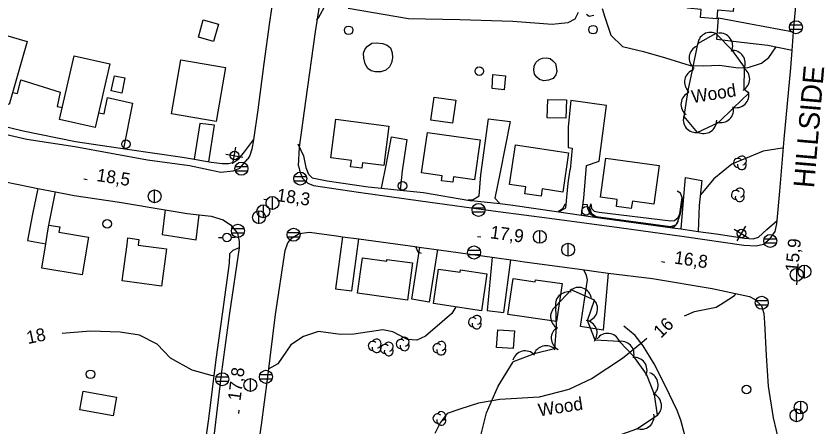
# Model space of a CAD drawing. Extents: x 646142 to 649934, y 5874075 to 5876351.
# Drawn here: x 647384.4 to 647570.1, y 5875028.6 to 5875124.3 of the extents above; entities that cross this region are included whole.
import ezdxf

# ---------------------------------------------------------------- set-up
doc = ezdxf.new("R2010")
doc.units = 0
for name, color, linetype in [('Niveau 1', 7, 'Continuous'), ('Niveau 15', 7, 'Continuous'), ('Niveau 19', 7, 'Continuous'), ('Niveau 2', 7, 'Continuous'), ('Niveau 21', 7, 'Continuous'), ('Niveau 22', 7, 'Continuous'), ('Niveau 3', 7, 'Continuous'), ('Niveau 31', 7, 'Continuous'), ('Niveau 36', 7, 'Continuous'), ('Niveau 37', 7, 'Continuous'), ('Niveau 4', 7, 'Continuous'), ('Niveau 44', 7, 'Continuous')]:
    doc.layers.add(name, color=color, linetype=linetype)

msp = doc.modelspace()

# ---------------------------------------------------------------- linework, layer by layer
at = {"layer": 'Niveau 1'}
for points in [[(647454.48, 5875123.38), (647454.96, 5875123.78), (647456.71, 5875127.05)], [(647521.11, 5875125.96), (647521.71, 5875123.96), (647523.15, 5875119.77), (647525.87, 5875117.15), (647530.71, 5875115.95), (647535.85, 5875114.49), (647541.6, 5875112.7), (647544.71, 5875112.63), (647548.5, 5875112.75), (647552.86, 5875112.18), (647555.16, 5875112.25), (647558.28, 5875113.27), (647559.99, 5875114.59), (647561.56, 5875116.82), (647561.66, 5875116.97)], [(647517.44, 5875124.66), (647518.06, 5875124.21), (647519.13, 5875124.43)]]:
    msp.add_lwpolyline(points, dxfattribs=at)
at = {"layer": 'Niveau 19'}
for points in [[(647565.42, 5875116.2), (647559.72, 5875117.37), (647553.61, 5875118.03), (647547.85, 5875118.73), (647548.24, 5875123.83), (647555.71, 5875122.38), (647565.77, 5875120.55)], [(647383.55, 5875106.43), (647384.69, 5875106.16), (647385.47, 5875109.33), (647394.66, 5875106.51), (647393.94, 5875103.15), (647395.18, 5875102.88)], [(647403.6, 5875101.66), (647404.92, 5875101.46), (647405.69, 5875105.26), (647411.53, 5875103.93), (647409.45, 5875093.33)], [(647513.77, 5875104.53), (647513.14, 5875098.37), (647513.21, 5875093.57), (647514.14, 5875093.42), (647513.66, 5875088.41)], [(647516.32, 5875077.77), (647516.82, 5875081.79), (647517.42, 5875089.35), (647520.44, 5875090.4), (647522.14, 5875103.37), (647513.77, 5875104.53)], [(647490.66, 5875081.19), (647492.41, 5875082.29), (647492.83, 5875087.18), (647494.61, 5875100.26), (647499.68, 5875099.61), (647497.29, 5875087.85), (647496.07, 5875081.73), (647497.27, 5875080.49)], [(647429.35, 5875090.22), (647430.69, 5875098.82), (647427.26, 5875099.19), (647425.93, 5875090.85)], [(647469.64, 5875084.1), (647470.79, 5875089.87), (647472, 5875096.1), (647475.56, 5875095.41), (647474.45, 5875088.15), (647473.97, 5875083.64)], [(647510.99, 5875078.56), (647512.63, 5875079.53), (647513.2, 5875085.24), (647513.66, 5875088.41)], [(647539.5, 5875074.57), (647540.09, 5875081.21), (647540.58, 5875086.57), (647544.37, 5875085.9), (647543.7, 5875080.07), (647543.48, 5875074.01)], [(647389.43, 5875084.02), (647388.19, 5875078.01), (647387.07, 5875071.9), (647391.32, 5875071.12)], [(647392.06, 5875075.48), (647393.55, 5875083.23)], [(647419.15, 5875079.04), (647418.45, 5875073.32), (647426.38, 5875072.03), (647427.06, 5875077.9)], [(647460.57, 5875072.76), (647458.92, 5875060.6), (647462.68, 5875060.16), (647464.35, 5875072.25)], [(647482.67, 5875069.76), (647480.75, 5875057.49), (647476.72, 5875058.18), (647478.58, 5875070.32)], [(647495.44, 5875068), (647494.29, 5875055.53), (647498.12, 5875055.1)], [(647499.7, 5875067.39), (647498.12, 5875055.1)], [(647522.54, 5875064.3), (647521.32, 5875050.98), (647516.06, 5875051.84), (647517.69, 5875062.69), (647517.49, 5875063.73), (647516.81, 5875065.03)]]:
    msp.add_lwpolyline(points, dxfattribs=at)
at = {"layer": 'Niveau 2'}
for points in [[(647563.41, 5875093.37), (647563.12, 5875093.41), (647558.66, 5875092.74), (647551.35, 5875089.71), (647547.12, 5875086.23), (647544.54, 5875083.09), (647543.97, 5875082.48)], [(647490.94, 5875081.37), (647489.86, 5875081.3)], [(647540.13, 5875081.64), (647539.91, 5875081.65), (647539.26, 5875077.84), (647538.49, 5875075.8), (647537.71, 5875074.91), (647537.31, 5875074.88)], [(647512.7, 5875080.27), (647512.42, 5875080.26), (647511.88, 5875079.29), (647510.81, 5875078.58)], [(647527.24, 5875076.25), (647526.62, 5875076.36), (647519.17, 5875077.47), (647518.3, 5875078.02), (647517.75, 5875079.35), (647517.66, 5875080.2), (647516.63, 5875080.25)], [(647477.81, 5875070.43), (647477.62, 5875070.3), (647478.08, 5875069.25), (647478.85, 5875068.92)], [(647540.35, 5875054.34), (647542.64, 5875055.34), (647547.73, 5875056.3), (647549.37, 5875057.33), (647551.99, 5875059.04), (647552.33, 5875059.51)], [(647486.99, 5875056.38), (647486.05, 5875054.84), (647483.8, 5875052.94), (647479.9, 5875049.61), (647477.84, 5875048.66), (647475.73, 5875048.8), (647472.29, 5875050.59), (647469.97, 5875051.06), (647463.21, 5875050.04), (647460.08, 5875049.96), (647454.94, 5875050.67), (647451.45, 5875049.51), (647448.51, 5875047.55), (647445.48, 5875043.09), (647443.32, 5875041.99)], [(647430.55, 5875040.39), (647430.17, 5875040.36), (647425.44, 5875041.63), (647420.43, 5875044.48), (647417.31, 5875047.69), (647413.19, 5875049.83), (647408.7, 5875050.54), (647401.76, 5875050.72), (647395.12, 5875050.18)], [(647531.52, 5875049.03), (647530.45, 5875048.11), (647525.88, 5875044.36), (647518.79, 5875039.73), (647513.34, 5875037.11), (647506.41, 5875035.38), (647497.2, 5875034.82), (647492.28, 5875033.92), (647487.87, 5875032.56), (647484.95, 5875031.52), (647483.3, 5875029.39), (647482.04, 5875026.89)]]:
    msp.add_lwpolyline(points, dxfattribs=at)
at = {"layer": 'Niveau 21'}
for points in [[(647450.3, 5875089.3), (647450.51, 5875088.27), (647451.16, 5875086.49), (647452.45, 5875085.24), (647453.79, 5875084.68), (647464.3, 5875083.18), (647478.7, 5875081.14), (647496.87, 5875078.67), (647508.8, 5875077.08), (647525.09, 5875074.88), (647540.22, 5875072.79), (647554.18, 5875070.82), (647557, 5875070.64), (647558.71, 5875071.04), (647560.32, 5875072.35), (647561.43, 5875073.97), (647561.83, 5875075.74), (647561.9, 5875076.55), (647562.54, 5875083.43), (647563.6, 5875095.54), (647565.09, 5875112.17), (647565.42, 5875116.2), (647565.77, 5875120.55), (647565.98, 5875123.22), (647567.26, 5875137.4)], [(647444.28, 5875128.19), (647443.51, 5875122.77), (647442.17, 5875113.19), (647440.75, 5875102.37), (647439.78, 5875095.38), (647439.4, 5875093.21), (647438.88, 5875091.71), (647438.43, 5875090.96)], [(647450.3, 5875089.3), (647450.48, 5875093.62), (647451.98, 5875104.36), (647454.26, 5875120.59), (647455.14, 5875126.53)], [(647373.66, 5875098.57), (647386.89, 5875095.51), (647398.13, 5875093.84), (647415.05, 5875090.71), (647424.87, 5875089.35), (647432.17, 5875087.83), (647435.02, 5875088.14), (647436.57, 5875088.76), (647438.43, 5875090.96)], [(647378.44, 5875086.24), (647387.58, 5875084.37), (647389.43, 5875084.02), (647393.55, 5875083.23), (647397.9, 5875082.4), (647408.53, 5875080.79), (647419.15, 5875079.04), (647424.26, 5875078.2), (647427.06, 5875077.9), (647429.9, 5875077.6), (647432.67, 5875076.72), (647434.42, 5875075.51), (647436.01, 5875073.59), (647436.44, 5875071.67), (647436.46, 5875070.16)], [(647440.08, 5875017.86), (647441.66, 5875028.86), (647443.01, 5875039.5), (647444.94, 5875054.59), (647447.12, 5875069.59), (647447.75, 5875071.38), (647448.8, 5875072.52), (647450.44, 5875073.49), (647452.85, 5875073.84), (647459.1, 5875072.96), (647460.57, 5875072.76), (647464.35, 5875072.25), (647476.33, 5875070.63), (647478.99, 5875070.27), (647483.55, 5875069.64), (647492.02, 5875068.49), (647495.44, 5875068), (647500.98, 5875067.21), (647503.01, 5875066.92), (647517.57, 5875064.93), (647519.19, 5875064.71), (647522.54, 5875064.3), (647532.87, 5875063.06), (647546.74, 5875060.73), (647555.45, 5875058.82), (647556.68, 5875058.24), (647558.24, 5875056.66), (647558.78, 5875054.87), (647559.01, 5875052.69), (647559.34, 5875045.08), (647559.85, 5875037.95), (647560.97, 5875030.53), (647562.41, 5875024.64)], [(647436.46, 5875070.16), (647434.19, 5875054.93), (647432.34, 5875041.24), (647430.5, 5875026.28), (647428.03, 5875008.35), (647426.81, 5874998.74), (647426.04, 5874997.17), (647424.61, 5874995.17), (647423, 5874993.86), (647420.63, 5874993.16), (647418.79, 5874992.86), (647416.91, 5874993.03), (647404.42, 5874995.61), (647383.56, 5874999.21)]]:
    msp.add_lwpolyline(points, dxfattribs=at)
at = {"layer": 'Niveau 22'}
for points in [[(647377.63, 5875099.47), (647386.01, 5875097.49), (647398.26, 5875095.01), (647410.32, 5875093.2), (647423.18, 5875091.36), (647425.05, 5875091.02), (647429.87, 5875090.12), (647431.2, 5875089.97), (647432.44, 5875089.82), (647433.93, 5875089.87), (647435.18, 5875090.12), (647436.37, 5875090.93), (647437.71, 5875092.56), (647439.78, 5875095.38)], [(647450.11, 5875094.46), (647451.45, 5875091.6), (647451.96, 5875088.88), (647452.59, 5875087.33), (647453.49, 5875086.49), (647456.93, 5875085.8), (647466.49, 5875084.44), (647469.64, 5875084.1), (647473.97, 5875083.64), (647479.43, 5875083.06), (647490.2, 5875081.24), (647490.66, 5875081.19), (647497.27, 5875080.49), (647499.73, 5875080.22), (647510.99, 5875078.56), (647516.32, 5875077.77), (647518.88, 5875077.39), (647537.54, 5875074.84), (647539.49, 5875074.57), (647543.47, 5875074.02), (647547.7, 5875073.42), (647554.33, 5875072.46), (647556.33, 5875072.31), (647557.57, 5875072.67), (647559.48, 5875074.47), (647561.9, 5875076.55)], [(647436.46, 5875070.16), (647434.92, 5875069.56), (647434.18, 5875068.8), (647434.06, 5875066.59), (647432.55, 5875055.25), (647431.02, 5875044.13), (647429.29, 5875030.33), (647427.32, 5875016.73), (647425.19, 5875001.15), (647424.74, 5874998.79), (647423.52, 5874997.05), (647422.03, 5874995.63), (647420.6, 5874994.8), (647419.45, 5874994.68), (647417.44, 5874994.95), (647413.76, 5874995.63), (647407.69, 5874996.77), (647402.43, 5874997.75), (647399.63, 5874998.28), (647391.01, 5874999.72), (647386.08, 5875000.55), (647380.56, 5875001.48)], [(647543.35, 5875011.9), (647541.49, 5875022.37), (647539.44, 5875030.01), (647538.62, 5875032.25), (647535.9, 5875037.92), (647533.24, 5875043.13), (647530.67, 5875047.32), (647528.78, 5875049.74), (647526.14, 5875051.88)]]:
    msp.add_lwpolyline(points, dxfattribs=at)
at = {"layer": 'Niveau 3'}
for p, q in [((647400.2, 5875086.25), (647401, 5875086.13)), ((647442.18, 5875081.55), (647442.97, 5875081.44)), ((647492.01, 5875072.85), (647492.8, 5875072.74)), ((647534.94, 5875066.98), (647535.73, 5875066.87)), ((647566.49, 5875061.58), (647566.56, 5875062.38)), ((647436.32, 5875031.52), (647436.42, 5875032.31))]:
    msp.add_line(p, q, dxfattribs=at)
at = {"layer": 'Niveau 31'}
for points in [[(647541.04, 5875126.05), (647541.99, 5875137.96), (647552.61, 5875137.1), (647551.66, 5875125.31), (647547.98, 5875125.61), (647547.82, 5875123.58), (647544.07, 5875123.88), (647544.23, 5875125.8), (647541.04, 5875126.05)], [(647431.58, 5875122.33), (647430.45, 5875118.31), (647426.97, 5875119.32), (647428.02, 5875123.39), (647431.58, 5875122.33), (647431.58, 5875122.33)], [(647374.44, 5875106), (647378.68, 5875120.71), (647386.98, 5875118.32), (647382.74, 5875103.61), (647374.44, 5875106)], [(647469.87, 5875117.8), (647470.97, 5875117.47), (647471.76, 5875116.79), (647472.12, 5875115.62), (647472.19, 5875114.51), (647471.98, 5875113.29), (647471.49, 5875112.37), (647470.61, 5875111.6), (647469.44, 5875111.24), (647468.14, 5875111.2), (647467.2, 5875111.44), (647466.46, 5875112.04), (647465.82, 5875113.08), (647465.49, 5875114.45), (647465.47, 5875115.56), (647465.72, 5875116.4), (647466.32, 5875117.14), (647467.4, 5875117.93), (647468.55, 5875117.95), (647469.87, 5875117.8), (647469.87, 5875117.8)], [(647394.54, 5875100.13), (647397.97, 5875114.98), (647406.23, 5875113.07), (647402.8, 5875098.22), (647394.54, 5875100.13)], [(647433.22, 5875112.27), (647431.06, 5875099.66), (647420.64, 5875101.44), (647422.8, 5875114.05), (647433.22, 5875112.27)], [(647507.21, 5875114.42), (647508.07, 5875114.51), (647508.96, 5875114.31), (647509.59, 5875113.79), (647510.19, 5875113.13), (647510.41, 5875112.38), (647510.52, 5875111.29), (647510.27, 5875110.49), (647509.67, 5875109.7), (647508.56, 5875109.25), (647507.51, 5875109.14), (647506.52, 5875109.42), (647505.83, 5875109.98), (647505.32, 5875110.7), (647505.13, 5875111.69), (647505.27, 5875112.58), (647505.67, 5875113.39), (647506.42, 5875114.09), (647507.21, 5875114.42), (647507.21, 5875114.42)], [(647409.77, 5875109.84), (647409.04, 5875106.25), (647406.57, 5875106.76), (647407.36, 5875110.32), (647409.77, 5875109.84), (647409.77, 5875109.84)], [(647498.57, 5875110.29), (647498.28, 5875107.04), (647495.41, 5875107.32), (647495.64, 5875110.62), (647498.57, 5875110.29), (647498.57, 5875110.29)], [(647481.92, 5875105.34), (647486.98, 5875104.62), (647486.22, 5875099.23), (647481.15, 5875099.95), (647481.92, 5875105.34)], [(647512.77, 5875104.66), (647512.63, 5875100.38), (647508.26, 5875100.53), (647508.4, 5875104.81), (647512.77, 5875104.66)], [(647458.99, 5875100.2), (647471.37, 5875098.55), (647470.15, 5875089.36), (647465.21, 5875090.01), (647465.04, 5875088.72), (647462.42, 5875089.06), (647462.62, 5875090.54), (647457.79, 5875091.18), (647458.99, 5875100.2)], [(647480.34, 5875097.11), (647492.67, 5875095.35), (647491.34, 5875086.05), (647486.45, 5875086.75), (647486.26, 5875085.46), (647483.6, 5875085.84), (647483.76, 5875086.97), (647478.99, 5875087.66), (647480.34, 5875097.11)], [(647500.87, 5875094.17), (647513.27, 5875092.35), (647511.92, 5875083.19), (647507.1, 5875083.9), (647506.86, 5875082.25), (647503.1, 5875082.8), (647503.33, 5875084.39), (647499.52, 5875084.95), (647500.87, 5875094.17)], [(647521.98, 5875091.09), (647534.44, 5875089.34), (647533.18, 5875080.34), (647528.15, 5875081.05), (647527.9, 5875079.33), (647524.42, 5875079.82), (647524.64, 5875081.41), (647520.7, 5875081.97), (647521.98, 5875091.09)], [(647399.8, 5875063.87), (647390.37, 5875065.47), (647391.32, 5875071.12), (647391.83, 5875074.12), (647392.06, 5875075.48), (647394.57, 5875075.05), (647394.36, 5875073.81), (647401.28, 5875072.64), (647399.8, 5875063.87)], [(647418.32, 5875061.23), (647409.15, 5875062.45), (647410.29, 5875070.98), (647410.49, 5875072.48), (647413.05, 5875072.14), (647412.87, 5875070.83), (647419.48, 5875069.95), (647418.32, 5875061.23)], [(647475.67, 5875057.99), (647464.03, 5875059.6), (647465.16, 5875067.84), (647470.85, 5875067.05), (647470.91, 5875067.49), (647476.87, 5875066.67), (647475.67, 5875057.99)], [(647492.92, 5875055.5), (647481.73, 5875057.16), (647482.92, 5875065.23), (647488, 5875064.48), (647488.08, 5875065.06), (647494.19, 5875064.15), (647492.92, 5875055.5)], [(647510.49, 5875052.98), (647499.12, 5875054.62), (647500.33, 5875063), (647505.46, 5875062.26), (647505.53, 5875062.75), (647511.76, 5875061.85), (647510.49, 5875052.98)], [(647496.48, 5875046.92), (647496.74, 5875051.09), (647500.62, 5875050.85), (647500.36, 5875046.67), (647496.48, 5875046.92)], [(647400.05, 5875036.75), (647407.8, 5875035.34), (647407.01, 5875031.01), (647399.26, 5875032.42), (647400.05, 5875036.75)]]:
    msp.add_lwpolyline(points, dxfattribs=at)
at = {"layer": 'Niveau 36'}
for p, q in [((647567.75, 5875122.07), (647564.87, 5875122.07)), ((647564.87, 5875121.15), (647567.75, 5875121.15)), ((647434.98, 5875089.73), (647435.65, 5875093.66)), ((647433.35, 5875092.03), (647437.28, 5875091.35)), ((647438.4, 5875089.09), (647435.52, 5875089.09)), ((647435.52, 5875088.17), (647438.4, 5875088.17)), ((647452.13, 5875086.76), (647449.25, 5875086.76)), ((647449.25, 5875085.84), (647452.13, 5875085.84)), ((647416.71, 5875080.68), (647416.71, 5875083.68)), ((647444.2, 5875079.14), (647444.2, 5875082.14)), ((647442.07, 5875077.2), (647442.07, 5875080.2)), ((647493.72, 5875079.46), (647490.84, 5875079.46)), ((647441.04, 5875075.81), (647441.04, 5875078.81)), ((647490.84, 5875078.54), (647493.72, 5875078.54)), ((647437.57, 5875074.59), (647434.69, 5875074.59)), ((647450.57, 5875073.69), (647447.69, 5875073.69)), ((647506.56, 5875071.23), (647506.56, 5875074.23)), ((647551.9, 5875074.54), (647555.31, 5875072.46)), ((647552.57, 5875071.8), (647554.64, 5875075.2)), ((647431.59, 5875072.61), (647432.59, 5875072.61)), ((647435.59, 5875072.61), (647434.59, 5875072.61)), ((647434.69, 5875073.67), (647437.57, 5875073.67)), ((647447.69, 5875072.77), (647450.57, 5875072.77)), ((647561.75, 5875072.23), (647558.87, 5875072.23)), ((647513.19, 5875068.23), (647513.19, 5875071.23)), ((647558.87, 5875071.31), (647561.75, 5875071.31)), ((647492.65, 5875069.54), (647489.77, 5875069.54)), ((647489.77, 5875068.62), (647492.65, 5875068.62)), ((647566.51, 5875062.38), (647566.51, 5875065.38)), ((647568.3, 5875063.13), (647568.3, 5875066.13)), ((647559.76, 5875057.81), (647556.88, 5875057.81)), ((647556.88, 5875056.89), (647559.76, 5875056.89)), ((647444.12, 5875040.54), (647441.24, 5875040.54)), ((647433.93, 5875039.99), (647431.05, 5875039.99)), ((647431.05, 5875039.07), (647433.93, 5875039.07)), ((647439.05, 5875036.66), (647439.05, 5875039.66)), ((647441.24, 5875039.62), (647444.12, 5875039.62)), ((647567.44, 5875031.44), (647567.44, 5875034.44)), ((647566.46, 5875029.6), (647566.46, 5875032.6))]:
    msp.add_line(p, q, dxfattribs=at)
for centre, radius in [((647518.97, 5875121.06), 1), ((647566.31, 5875121.62), 1.52), ((647461.97, 5875120.91), 1), ((647492.45, 5875111.38), 1), ((647410.02, 5875094.35), 1), ((647435.32, 5875091.69), 1), ((647436.96, 5875088.64), 1.52), ((647450.69, 5875086.31), 1.52), ((647474.53, 5875084.61), 1), ((647416.7, 5875082.19), 1.5), ((647444.19, 5875080.65), 1.5), ((647442.06, 5875078.71), 1.5), ((647492.28, 5875079.01), 1.52), ((647517.35, 5875078.81), 1), ((647441.04, 5875077.32), 1.5), ((647405.66, 5875075.79), 1), ((647436.13, 5875074.14), 1.52), ((647449.13, 5875073.24), 1.52), ((647506.55, 5875072.74), 1.5), ((647553.61, 5875073.5), 1), ((647433.58, 5875072.61), 1), ((647560.31, 5875071.78), 1.52), ((647491.21, 5875069.09), 1.52), ((647513.18, 5875069.74), 1.5), ((647566.5, 5875063.89), 1.5), ((647568.29, 5875064.64), 1.5), ((647558.32, 5875057.36), 1.52), ((647401.74, 5875040.68), 1), ((647432.49, 5875039.54), 1.52), ((647442.68, 5875040.09), 1.52), ((647439.04, 5875038.17), 1.5), ((647554.78, 5875037.16), 1), ((647567.43, 5875032.95), 1.5), ((647566.45, 5875031.11), 1.5)]:
    msp.add_circle(centre, radius, dxfattribs=at)
at = {"layer": 'Niveau 37'}
for points in [[(647518.49, 5875080.4), (647518.6, 5875079.37), (647519.25, 5875078.75), (647520.43, 5875078.52), (647537.16, 5875076.48), (647537.97, 5875076.56), (647538.83, 5875077.22), (647539.2, 5875078.07), (647539.73, 5875081.93), (647539.39, 5875082.93), (647538.64, 5875083.43)], [(647538.83, 5875077.22), (647538.77, 5875076.3), (647538.21, 5875075.43), (647537.08, 5875075.09), (647519.73, 5875077.41), (647518.74, 5875078.01), (647518.16, 5875079.1), (647518.49, 5875080.4)]]:
    msp.add_lwpolyline(points, dxfattribs=at)
at = {"layer": 'Niveau 4'}
msp.add_lwpolyline([(647515.53, 5875125.05), (647514.76, 5875123.48), (647513.12, 5875122.62), (647509.47, 5875122.24), (647500.3, 5875122.98), (647487.93, 5875123.39), (647475.93, 5875123.61), (647461.86, 5875126.01)], dxfattribs=at)
at = {"layer": 'Niveau 44'}
for points in [[(647554.25, 5875107.1), (647554.34, 5875112.28), (647551.5, 5875116.21), (647547.61, 5875120.15), (647543.38, 5875117.77), (647542.11, 5875111.58), (647541.08, 5875106.84), (647540.12, 5875100.78), (647543.24, 5875097.06), (647548.22, 5875099.43), (647551.72, 5875102.8), (647555.33, 5875106.26), (647554.25, 5875107.1)], [(647489.34, 5875020.65), (647493.39, 5875017.97), (647497.98, 5875021.17), (647501.2, 5875018.92), (647506.51, 5875018.69), (647511.14, 5875020.16), (647515.45, 5875023.08), (647519.39, 5875025.91), (647524.64, 5875026.34), (647529.21, 5875027.98), (647534.03, 5875031.17), (647533.35, 5875035.98), (647531.43, 5875040.74), (647528.51, 5875044.85), (647525.15, 5875048.35), (647519.47, 5875048.68), (647517.68, 5875053.2), (647519.29, 5875057.96), (647513.91, 5875060.4), (647510.21, 5875056.47), (647510.38, 5875051.62), (647509.95, 5875046.62), (647505.23, 5875045.46), (647500.36, 5875043.56)], [(647492.7, 5875026.1), (647494.1, 5875031.67), (647496.85, 5875037.9), (647500.36, 5875043.56)]]:
    msp.add_lwpolyline(points, dxfattribs=at)
for centre, radius, start, end in [((647546.36, 5875117.43), 3, 59.4455, 179.4235), ((647548.56, 5875117.26), 3, 335.8544, 95.8323), ((647544.39, 5875114.44), 3, 112.1187, 232.0966), ((647551.49, 5875113.21), 3, 335.8544, 95.8323), ((647543.32, 5875108.84), 3, 107.7523, 227.7303), ((647552.52, 5875109.54), 3, 299.2759, 59.2538), ((647542.49, 5875103.62), 3, 113.3375, 233.3154), ((647552.35, 5875105.85), 3, 253.9032, 13.8811), ((647548.75, 5875102.38), 3, 253.9032, 13.8811), ((647543.03, 5875100.05), 3, 159.9911, 279.969), ((647544.82, 5875099.84), 3, 242.1174, 2.0953), ((647552.79, 5875090), 1.05, 44.1154, 269.804), ((647553.69, 5875090.53), 1.05, 282.2692, 149.7263), ((647553.69, 5875089.48), 1.05, 166.9369, 29.6212), ((647552.3, 5875082.52), 1.05, 44.1154, 269.804), ((647553.2, 5875083.05), 1.05, 282.2692, 149.7263), ((647553.2, 5875082), 1.05, 166.9369, 29.6212), ((647515.64, 5875057.95), 3, 11.2574, 131.2353), ((647513.2, 5875056.9), 3, 76.6273, 196.6053), ((647517.03, 5875055.98), 3, 287.3667, 47.3446), ((647512.06, 5875054.1), 3, 121.9486, 241.9265), ((647490.94, 5875052.85), 1.05, 44.1154, 269.804), ((647491.84, 5875053.38), 1.05, 282.2692, 149.7263), ((647516.93, 5875050.29), 3, 321.5693, 81.5472), ((647491.84, 5875052.33), 1.05, 166.9369, 29.6212), ((647512.23, 5875049.11), 3, 121.9486, 241.9265), ((647522.39, 5875047.23), 3, 24.1306, 144.1086), ((647467.58, 5875047.33), 1.05, 44.1154, 269.804), ((647468.48, 5875047.86), 1.05, 282.2692, 149.7263), ((647471.33, 5875047.11), 1.05, 282.2692, 149.7263), ((647474.12, 5875047.75), 1.05, 44.1154, 269.804), ((647475.02, 5875047.23), 1.05, 166.9369, 29.6212), ((647475.02, 5875048.28), 1.05, 282.2692, 149.7263), ((647482.67, 5875046.76), 1.05, 44.1154, 269.804), ((647483.57, 5875047.29), 1.05, 282.2692, 149.7263), ((647525.55, 5875045.38), 3, 343.8005, 103.7785), ((647468.48, 5875046.81), 1.05, 166.9369, 29.6212), ((647470.43, 5875046.58), 1.05, 44.1154, 269.804), ((647471.33, 5875046.06), 1.05, 166.9369, 29.6212), ((647483.57, 5875046.24), 1.05, 166.9369, 29.6212), ((647503.15, 5875043.14), 3, 43.8367, 163.8147), ((647508.01, 5875044.33), 3, 43.8367, 163.8147), ((647528.57, 5875041.64), 3, 336.6191, 96.597), ((647531.17, 5875038.23), 3, 309.3532, 69.3311), ((647531.94, 5875033.33), 3, 308.0958, 68.0737), ((647482.69, 5875030.39), 1.05, 44.1154, 269.804), ((647483.59, 5875030.92), 1.05, 282.2692, 149.7263), ((647530.22, 5875030.87), 3, 249.9547, 9.9326), ((647483.59, 5875029.87), 1.05, 166.9369, 29.6212)]:
    msp.add_arc(centre, radius, start, end, dxfattribs=at)

# ---------------------------------------------------------------- texts
at = {"layer": 'Niveau 15'}
msp.add_text('HILLSIDE', height=4.8, rotation=85.1286, dxfattribs=at).set_placement((647570.51, 5875084))
at = {"layer": 'Niveau 2'}
for s, rotation, p in [('16', 43.847, (647534.81, 5875048.96)), ('18', 11.7366, (647387.15, 5875047.72))]:
    msp.add_text(s, height=3, rotation=rotation, dxfattribs=at).set_placement(p)
at = {"layer": 'Niveau 3'}
for s, rotation, p in [('18,5 ', 351.181, (647403.04, 5875085.77)), ('18,3 ', 351.699, (647445.03, 5875081.1)), ('17,9 ', 352.2955, (647494.86, 5875072.42)), ('15,9 ', 84.6533, (647566.79, 5875064.45)), ('16,8 ', 351.6289, (647537.78, 5875066.53)), ('17,8 ', 82.7081, (647436.73, 5875034.37))]:
    msp.add_text(s, height=3, rotation=rotation, dxfattribs=at).set_placement(p)
at = {"layer": 'Niveau 44'}
for p in [(647542.18, 5875103.92), (647506.43, 5875030.84)]:
    msp.add_text('Wood', height=3, rotation=8.9405, dxfattribs=at).set_placement(p)

doc.saveas('drawing.dxf')
